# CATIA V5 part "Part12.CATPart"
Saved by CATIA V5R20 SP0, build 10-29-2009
Part number: Parallel Pin Unhardened_DIN_Parallel Pin ISO 2338 - 2 h6 x 10 - St
Revision: ANY
Definition: UNKNOWN
Nomenclature: Parallel Pin Unhardened_DIN_Parallel Pin ISO 2338 - 2 h6 x 10 - St
Source: Unknown
Bounding box of the stored display mesh (mm): x 0 to 10, y -1 to 1, z -1 to 1
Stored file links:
  C:\Users\Utente\Desktop\IO LAVORO\3D X SITO CF\CUMSA\3D files BA\BA 101822\Part12.CATPart
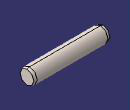
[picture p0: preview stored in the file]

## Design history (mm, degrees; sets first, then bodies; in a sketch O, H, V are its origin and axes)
Body1 "Base-Revolve" (main body)
  Solid1: solid without history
